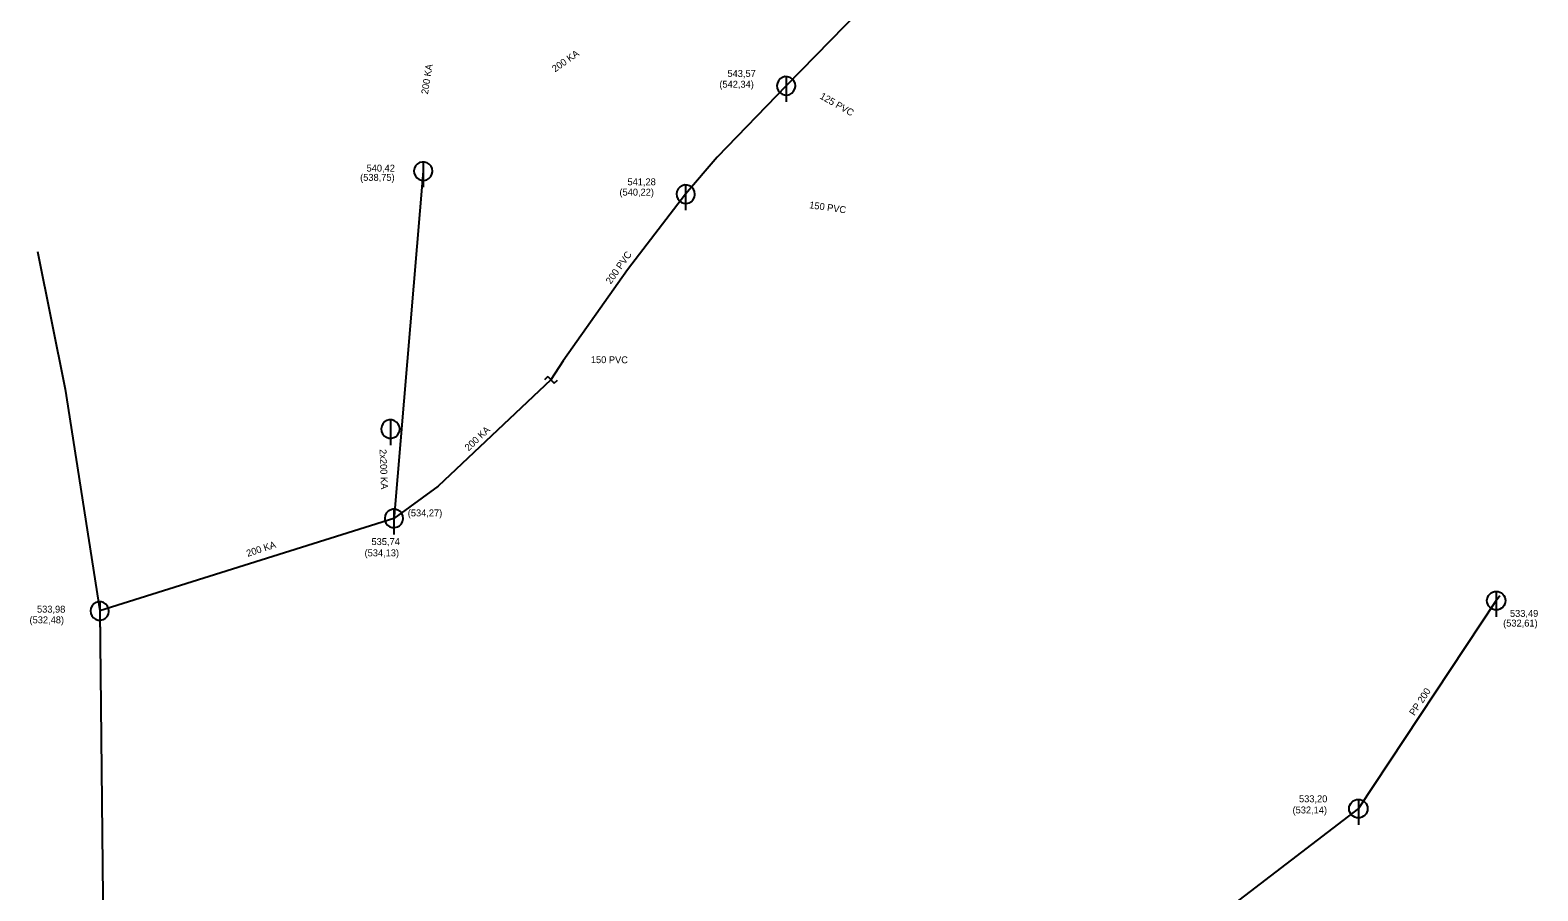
# Model space of a CAD drawing. Extents: x -476058 to -471893, y -1155786 to -1152000.
# Drawn here: x -473096.5 to -472933.1, y -1153724.5 to -1153631.2 of the extents above; entities that cross this region are included whole.
import ezdxf

# ---------------------------------------------------------------- set-up
doc = ezdxf.new("R2010")
doc.units = 0
for name, color, linetype in [('Vrstva 10', 7, 'Continuous'), ('Vrstva 18', 7, 'Continuous'), ('Vrstva 19', 7, 'Continuous'), ('Vrstva 3', 7, 'Continuous'), ('Vrstva 4', 7, 'Continuous'), ('Vrstva 45', 7, 'Continuous'), ('Vrstva 50', 7, 'Continuous')]:
    doc.layers.add(name, color=color, linetype=linetype)

msp = doc.modelspace()

# ---------------------------------------------------------------- linework, layer by layer
at = {"layer": 'Vrstva 10'}
for p, q in [((-473014.56, -1153636.23), (-473014.56, -1153638.97)), ((-473053.88, -1153645.47), (-473053.88, -1153648.22)), ((-473025.45, -1153647.96), (-473025.45, -1153650.71)), ((-473040.39, -1153668.74), (-473040.75, -1153669.08)), ((-473040.39, -1153668.74), (-473039.7, -1153669.46)), ((-473039.7, -1153669.46), (-473039.34, -1153669.12)), ((-473057.42, -1153673.42), (-473057.42, -1153676.17)), ((-473057.05, -1153683.1), (-473057.05, -1153685.85)), ((-472937.65, -1153692.01), (-472937.65, -1153694.76)), ((-473088.92, -1153693.13), (-473088.92, -1153695.88)), ((-472952.58, -1153714.55), (-472952.58, -1153717.3))]:
    msp.add_line(p, q, dxfattribs=at)
for points in [[(-473013.56, -1153637.23), (-473013.6, -1153636.95), (-473013.72, -1153636.69), (-473013.9, -1153636.47), (-473014.13, -1153636.32), (-473014.4, -1153636.24), (-473014.69, -1153636.23), (-473014.96, -1153636.31), (-473015.2, -1153636.46), (-473015.39, -1153636.67), (-473015.51, -1153636.92), (-473015.56, -1153637.2), (-473015.53, -1153637.48), (-473015.42, -1153637.74), (-473015.24, -1153637.96), (-473015.01, -1153638.12), (-473014.74, -1153638.21), (-473014.46, -1153638.22), (-473014.18, -1153638.15), (-473013.94, -1153638.01), (-473013.75, -1153637.81), (-473013.62, -1153637.56), (-473013.56, -1153637.28), (-473013.56, -1153637.23)], [(-473052.88, -1153646.47), (-473052.92, -1153646.19), (-473053.03, -1153645.93), (-473053.22, -1153645.72), (-473053.45, -1153645.56), (-473053.72, -1153645.48), (-473054, -1153645.48), (-473054.28, -1153645.55), (-473054.52, -1153645.7), (-473054.71, -1153645.91), (-473054.83, -1153646.16), (-473054.88, -1153646.44), (-473054.84, -1153646.72), (-473054.73, -1153646.98), (-473054.56, -1153647.2), (-473054.33, -1153647.36), (-473054.06, -1153647.45), (-473053.78, -1153647.47), (-473053.5, -1153647.4), (-473053.26, -1153647.26), (-473053.06, -1153647.05), (-473052.93, -1153646.8), (-473052.88, -1153646.53), (-473052.88, -1153646.47)], [(-473024.45, -1153648.96), (-473024.48, -1153648.68), (-473024.6, -1153648.43), (-473024.78, -1153648.21), (-473025.02, -1153648.06), (-473025.29, -1153647.98), (-473025.57, -1153647.97), (-473025.84, -1153648.05), (-473026.08, -1153648.19), (-473026.27, -1153648.4), (-473026.4, -1153648.66), (-473026.45, -1153648.94), (-473026.41, -1153649.22), (-473026.3, -1153649.48), (-473026.13, -1153649.7), (-473025.9, -1153649.86), (-473025.63, -1153649.95), (-473025.35, -1153649.96), (-473025.07, -1153649.89), (-473024.83, -1153649.75), (-473024.63, -1153649.55), (-473024.5, -1153649.3), (-473024.45, -1153649.02), (-473024.45, -1153648.96)], [(-473056.42, -1153674.42), (-473056.46, -1153674.14), (-473056.58, -1153673.88), (-473056.76, -1153673.67), (-473057, -1153673.51), (-473057.27, -1153673.43), (-473057.55, -1153673.43), (-473057.82, -1153673.5), (-473058.06, -1153673.65), (-473058.25, -1153673.86), (-473058.37, -1153674.11), (-473058.42, -1153674.39), (-473058.39, -1153674.67), (-473058.28, -1153674.93), (-473058.1, -1153675.15), (-473057.87, -1153675.31), (-473057.6, -1153675.4), (-473057.32, -1153675.42), (-473057.05, -1153675.35), (-473056.8, -1153675.21), (-473056.61, -1153675), (-473056.48, -1153674.75), (-473056.42, -1153674.48), (-473056.42, -1153674.42)], [(-473056.05, -1153684.1), (-473056.09, -1153683.82), (-473056.21, -1153683.57), (-473056.39, -1153683.35), (-473056.63, -1153683.2), (-473056.9, -1153683.11), (-473057.18, -1153683.11), (-473057.45, -1153683.19), (-473057.69, -1153683.33), (-473057.88, -1153683.54), (-473058, -1153683.8), (-473058.05, -1153684.07), (-473058.02, -1153684.35), (-473057.91, -1153684.61), (-473057.73, -1153684.83), (-473057.5, -1153685), (-473057.23, -1153685.09), (-473056.95, -1153685.1), (-473056.68, -1153685.03), (-473056.43, -1153684.89), (-473056.24, -1153684.69), (-473056.11, -1153684.44), (-473056.05, -1153684.16), (-473056.05, -1153684.1)], [(-473087.92, -1153694.13), (-473087.96, -1153693.85), (-473088.08, -1153693.6), (-473088.26, -1153693.38), (-473088.49, -1153693.23), (-473088.77, -1153693.14), (-473089.05, -1153693.14), (-473089.32, -1153693.22), (-473089.56, -1153693.36), (-473089.75, -1153693.57), (-473089.87, -1153693.83), (-473089.92, -1153694.1), (-473089.89, -1153694.39), (-473089.78, -1153694.65), (-473089.6, -1153694.86), (-473089.37, -1153695.03), (-473089.1, -1153695.12), (-473088.82, -1153695.13), (-473088.55, -1153695.06), (-473088.3, -1153694.92), (-473088.11, -1153694.72), (-473087.98, -1153694.47), (-473087.92, -1153694.19), (-473087.92, -1153694.13)]]:
    msp.add_lwpolyline(points, dxfattribs=at)
for centre in [(-472937.65, -1153693.01), (-472952.58, -1153715.55)]:
    msp.add_circle(centre, 1, dxfattribs=at)
at = {"layer": 'Vrstva 45'}
for p, q in [((-473014.56, -1153637.23), (-473022.03, -1153644.94)), ((-473022.03, -1153644.94), (-473025.45, -1153648.96)), ((-473025.45, -1153648.96), (-473031.76, -1153657.17)), ((-473031.76, -1153657.17), (-473038.72, -1153667.03)), ((-473040.05, -1153669.1), (-473052.25, -1153680.62)), ((-473052.25, -1153680.62), (-473057.05, -1153684.1))]:
    msp.add_line(p, q, dxfattribs=at)
for points in [[(-472987.5, -1153609.53), (-473014.56, -1153637.23)], [(-473038.72, -1153667.03), (-473040.05, -1153669.1)], [(-473057.05, -1153684.1), (-473088.92, -1153694.13)], [(-473088.92, -1153694.13), (-473088.54, -1153728.59)]]:
    msp.add_lwpolyline(points, dxfattribs=at)
at = {"layer": 'Vrstva 50'}
for p, q in [((-473095.67, -1153655.17), (-473092.66, -1153670.1)), ((-473092.66, -1153670.1), (-473088.92, -1153694.13))]:
    msp.add_line(p, q, dxfattribs=at)
for points in [[(-473053.88, -1153646.47), (-473057.03, -1153683.85)], [(-473057.03, -1153683.85), (-473057.05, -1153684.1)], [(-472937.65, -1153693.01), (-472937.26, -1153692.44)], [(-472937.65, -1153693.01), (-472952.58, -1153715.55)], [(-472952.58, -1153715.55), (-472986.21, -1153741.33)]]:
    msp.add_lwpolyline(points, dxfattribs=at)

# ---------------------------------------------------------------- texts
at = {"layer": 'Vrstva 18'}
for s, rotation, p in [('200 PVC', 54.7984, (-473033.56, -1153658.77)), ('150 PVC', 359.6557, (-473035.72, -1153667.27)), ('200 KA', 43.3579, (-473048.96, -1153676.84)), ('200 KA', 18.3682, (-473072.89, -1153688.28))]:
    msp.add_text(s, height=0.75, rotation=rotation, dxfattribs=at).set_placement(p)
at = {"layer": 'Vrstva 19'}
for s, rotation, p in [('200 KA', 35.2527, (-473039.6, -1153635.78)), ('200 KA', 80.9356, (-473053.37, -1153638.18)), ('125 PVC', 330.3786, (-473010.99, -1153638.56)), ('150 PVC', 351.826, (-473012.1, -1153650.48)), ('2x200 KA', 272.191, (-473058.61, -1153676.61)), ('PP 200', 56.4916, (-472946.51, -1153705.54))]:
    msp.add_text(s, height=0.75, rotation=rotation, dxfattribs=at).set_placement(p)
at = {"layer": 'Vrstva 3'}
for s, p in [('543,57 ', (-473020.92, -1153636.26)), ('540,42 ', (-473060.01, -1153646.52)), ('541,28 ', (-473031.75, -1153648)), ('535,74 ', (-473059.48, -1153686.99)), ('533,98', (-473095.71, -1153694.31)), ('533,49', (-472936.16, -1153694.77)), ('533,20', (-472959.01, -1153714.86))]:
    msp.add_text(s, height=0.75, dxfattribs=at).set_placement(p)
at = {"layer": 'Vrstva 4'}
for s, p in [('(542,34)', (-473021.8, -1153637.43)), ('(538,75)', (-473060.71, -1153647.52)), ('(540,22)', (-473032.62, -1153649.12)), ('(534,27)', (-473055.55, -1153683.88)), ('(534,13)', (-473060.23, -1153688.21)), ('(532,48)', (-473096.52, -1153695.47)), ('(532,61)', (-472936.9, -1153695.82)), ('(532,14)', (-472959.71, -1153716.07))]:
    msp.add_text(s, height=0.75, dxfattribs=at).set_placement(p)

doc.saveas('drawing.dxf')
